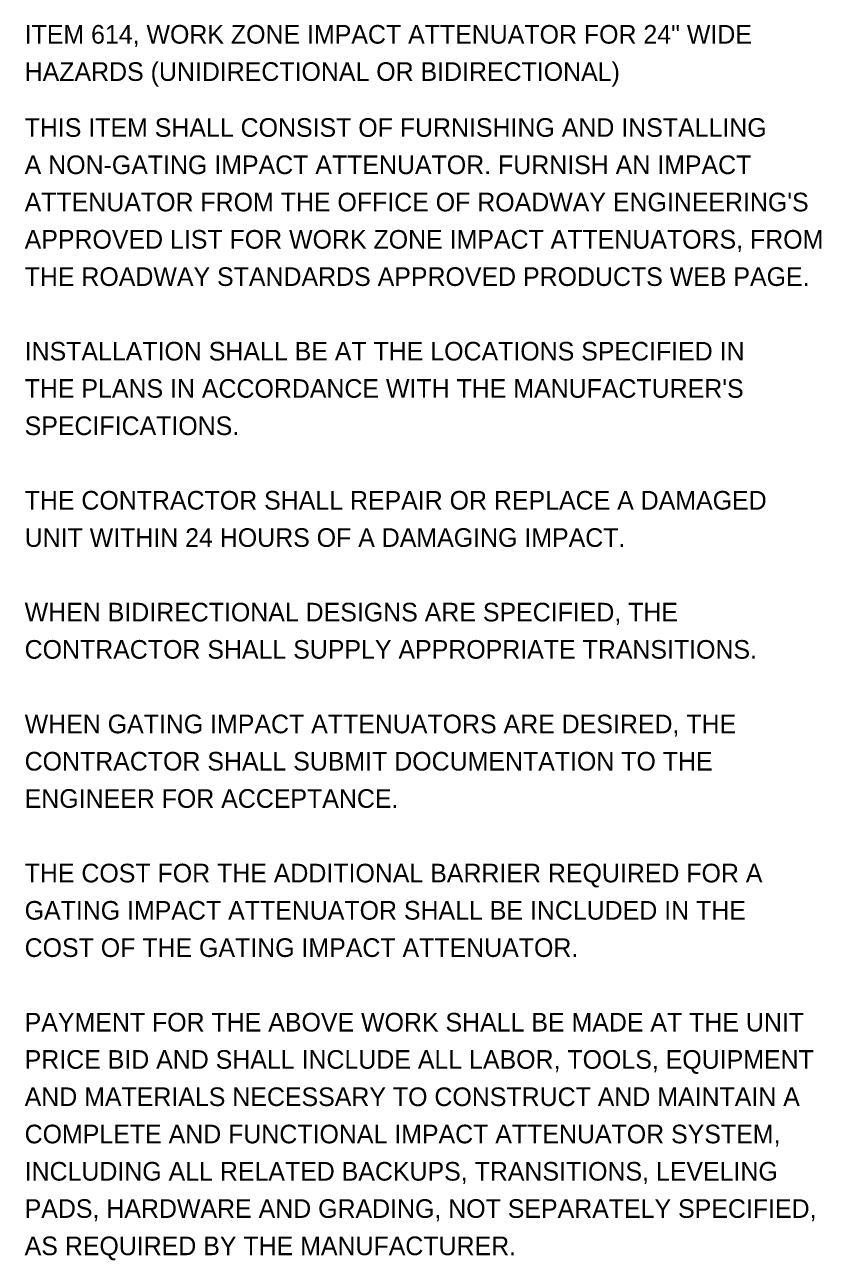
# Model space of a CAD drawing. Extents: x -10.6 to 44.1, y -11.1 to 22.
# Drawn here: x 9.82 to 15.81, y -11.12 to -1.84 of the extents above; entities that cross this region are included whole.
import ezdxf

# ---------------------------------------------------------------- set-up
doc = ezdxf.new("R2010")
doc.units = 0
doc.layers.add('SH_Text', color=7, linetype='Continuous')

msp = doc.modelspace()

# ---------------------------------------------------------------- texts
at = {"layer": 'SH_Text'}
for s, p in [('ITEM 614, WORK ZONE IMPACT ATTENUATOR FOR 24" WIDE', (9.82, -1.9852)), ('HAZARDS (UNIDIRECTIONAL OR BIDIRECTIONAL)', (9.82, -2.2652)), ('THIS ITEM SHALL CONSIST OF FURNISHING AND INSTALLING', (9.82, -2.6852)), ('A NON-GATING IMPACT ATTENUATOR. FURNISH AN IMPACT', (9.82, -2.9652)), ("ATTENUATOR FROM THE OFFICE OF ROADWAY ENGINEERING'S", (9.82, -3.2452)), ('APPROVED LIST FOR WORK ZONE IMPACT ATTENUATORS, FROM', (9.82, -3.5252)), ('THE ROADWAY STANDARDS APPROVED PRODUCTS WEB PAGE.', (9.82, -3.8052)), ('INSTALLATION SHALL BE AT THE LOCATIONS SPECIFIED IN', (9.82, -4.3652)), ("THE PLANS IN ACCORDANCE WITH THE MANUFACTURER'S", (9.82, -4.6452)), ('SPECIFICATIONS.', (9.82, -4.9252)), ('THE CONTRACTOR SHALL REPAIR OR REPLACE A DAMAGED', (9.82, -5.4852)), ('UNIT WITHIN 24 HOURS OF A DAMAGING IMPACT.', (9.82, -5.7652)), ('WHEN BIDIRECTIONAL DESIGNS ARE SPECIFIED, THE', (9.82, -6.3252)), ('CONTRACTOR SHALL SUPPLY APPROPRIATE TRANSITIONS.', (9.82, -6.6052)), ('WHEN GATING IMPACT ATTENUATORS ARE DESIRED, THE', (9.82, -7.1652)), ('CONTRACTOR SHALL SUBMIT DOCUMENTATION TO THE', (9.82, -7.4452)), ('ENGINEER FOR ACCEPTANCE.', (9.82, -7.7252)), ('THE COST FOR THE ADDITIONAL BARRIER REQUIRED FOR A', (9.82, -8.2852)), ('GATING IMPACT ATTENUATOR SHALL BE INCLUDED IN THE', (9.82, -8.5652)), ('COST OF THE GATING IMPACT ATTENUATOR.', (9.82, -8.8452)), ('PAYMENT FOR THE ABOVE WORK SHALL BE MADE AT THE UNIT', (9.82, -9.4052)), ('PRICE BID AND SHALL INCLUDE ALL LABOR, TOOLS, EQUIPMENT', (9.82, -9.6852)), ('AND MATERIALS NECESSARY TO CONSTRUCT AND MAINTAIN A', (9.82, -9.9652)), ('COMPLETE AND FUNCTIONAL IMPACT ATTENUATOR SYSTEM,', (9.82, -10.2452)), ('INCLUDING ALL RELATED BACKUPS, TRANSITIONS, LEVELING', (9.82, -10.5252)), ('PADS, HARDWARE AND GRADING, NOT SEPARATELY SPECIFIED,', (9.82, -10.8052)), ('AS REQUIRED BY THE MANUFACTURER.', (9.82, -11.0852))]:
    msp.add_text(s, height=0.14, dxfattribs=at).set_placement(p)

doc.saveas('drawing.dxf')
